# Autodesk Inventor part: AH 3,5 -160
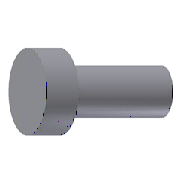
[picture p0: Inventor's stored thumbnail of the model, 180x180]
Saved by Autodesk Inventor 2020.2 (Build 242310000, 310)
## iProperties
Manager: www.cadconsulting.pl
Company: Fabian Stasiak CAD Consulting
Created: 2014-02
Part Number: AH 3,5 -160
Material: DIN 1.2210
Description: Ejector pins-hardened
Document SubType Name: Modeling
Standard: DIN 1530/ISO 6751
Designer: F.Stasiak
Standard Revision: 1
Manufacturer: DME
Language: pl-PL
Size Designation: 3,5 -160
Categories: <MemberInstance><Categories><Category DisplayName="Forma wtryskowa" InternalName="349578f2-f4d4-4954-8c09-8e99297a61c0" Mnemonic="MOLD"><Category DisplayName="K
Mass: 0.191827 g
Surface Area: 2.51725 cm^2
Volume: 0.191827 cm^3
Density: 7.85 g/cm^3
Appearance: Aluminium - ciemne
Catalog Web Link: www.expertbooks.pl
IsCustomPart: 1
Author: F.Stasiak
Subject: Zbiór ćwiczeń. Autodesk Inventor 2020. Kurs Professional
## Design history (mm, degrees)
sketch "Sketch1"
  geometry: L1 (0, 3.5)-(3, 3.5); L2 (0, 0)-(0, 3.5); L3 (3, 1.75)-(160, 1.75); L4 (160, 1.75)-(160, 0); L5 (0, 0)-(160, 0); L6 (3, 3.5)-(3, 1.75); 2 further points
  constraints: 12 end point, 4 point on line, 2 horizontal, 2 perpendicular, 1 coincident
  dimensions: "d6" = 3 distance of L1.start L1.end (derived); "d9" = 160 distance between parallel lines of L4 L2 (derived); "d10" = 7 diameter of L1 L5 (derived); "d13" = 3.5 diameter of L3 L5 (derived)
revolve "Revolution1" sketch "Sketch1" stored, may be unused: angle "d11" = 90 deg
fillet "Fillet1" dims "d29" = 0.3 (derived)
workplane "Work Plane1"
sketch "Sketch2"
  geometry: L1 (3.5, -1.5)-(-3.5, -1.5) reference; L2 (-3.5, -1.5)-(-3.5, 1.5) reference; 4 further points
  constraints: 2 midpoint, 1 horizontal alignment, 1 vertical alignment
hole "Anti_Rotary Hole" sketch "Sketch2" at (0, 0) diameter "d44" = 0.55 (derived); stored, may be unused: countersink angle "d48" = 90 deg, drill point angle "d50" = 118 deg; dims "d45" = 6, "d46" = 4, "d47" = 2, "d49" = 0.825 (derived)
sketch "Sketch3"
  geometry: L1 (-2.05, 2.837)-(-2.05, -2.837); A1 r 3.5 centre (0, 0) between (-2.05, 2.837) and (-2.05, -2.837) reference; 1 further point
  constraints: 2 end point, 2 point on circle, 1 vertical
  dimensions: "d55" = 2.05 distance from line of point (0, 0) L1 (derived)
extrude "Anti_Rotary Plane" cut sketch "Sketch3" distance "d42" = 3.3 (derived); taper "d43" = 0 deg
body "Solid1"
node "Projected Loop1"
other parameters: "d15" = 0, "d24" = 0, "P" = 3.5 [user parameter], "T_" = 3 [user parameter], "H_" = 7 [user parameter], "R" = 0.3 [user parameter], "Anti_Rotary_P" = 2.05 [user parameter], "Anti_Rotary_D" = 0.55 [user parameter], "d51" = 0, "d54" = 0, "d56" = 0, "d57" = 0
